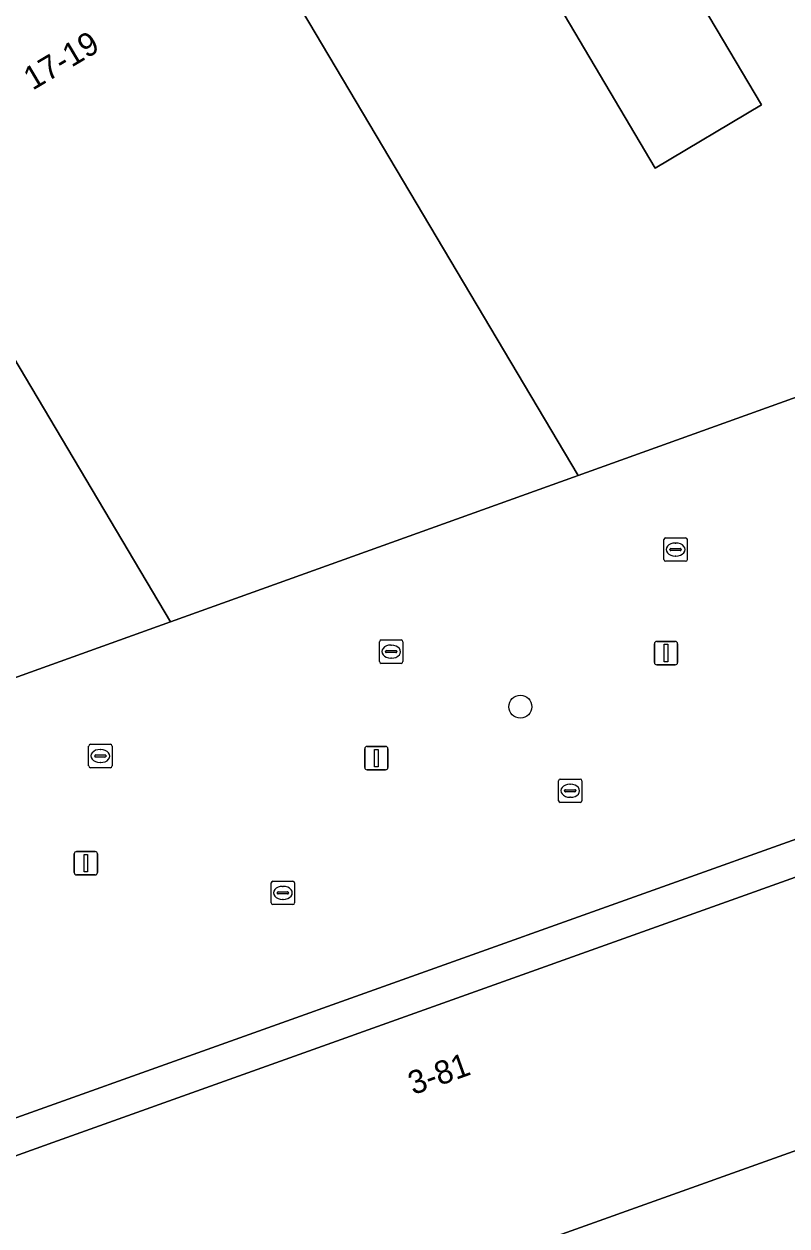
# Model space of a CAD drawing. Extents: x 159499 to 160349, y 382524 to 383273.
# Drawn here: x 159623.7 to 159656.3, y 382937.3 to 382988.7 of the extents above; entities that cross this region are included whole.
import ezdxf

# ---------------------------------------------------------------- set-up
doc = ezdxf.new("R2010")
doc.units = 0
for name, color, linetype in [('IMGEO_Boom', 7, 'Continuous'), ('IMGEO_Erf', 7, 'Continuous'), ('IMGEO_Groenvoorziening', 7, 'Continuous'), ('IMGEO_Kolk', 7, 'Continuous'), ('IMGEO_Lichtmast', 7, 'Continuous'), ('IMGEO_Pand', 7, 'Continuous'), ('IMGEO_Pand_nummerreeks', 7, 'Continuous'), ('IMGEO_Parkeervlak_open', 7, 'Continuous'), ('IMGEO_Voetpad_open', 7, 'Continuous')]:
    doc.layers.add(name, color=color, linetype=linetype)

msp = doc.modelspace()

# ---------------------------------------------------------------- linework, layer by layer
at = {"layer": 'IMGEO_Boom'}
msp.add_circle((159644.9, 382959.472), 0.489, dxfattribs=at)
at = {"layer": 'IMGEO_Erf'}
msp.add_lwpolyline([(159644.178, 383001.574), (159640.635, 382999.47), (159642.929, 382995.586), (159650.661, 382982.501), (159655.211, 382985.203), (159647.452, 382998.271), (159646.481, 382997.695)], close=True, dxfattribs=at)
at = {"layer": 'IMGEO_Groenvoorziening'}
msp.add_lwpolyline([(159685.537, 382944.38), (159682.676, 382958.981), (159682.454, 382960.802), (159675.818, 382961.931), (159676.134, 382961.046), (159680.442, 382948.993), (159609.134, 382923.507), (159606.674, 382930.391), (159601.595, 382928.556), (159605.894, 382916.702)], dxfattribs=at)
at = {"layer": 'IMGEO_Kolk'}
for p, q in [((159651.11, 382966.69), (159651.962, 382966.69)), ((159651.035, 382965.764), (159651.035, 382966.616)), ((159651.294, 382966.184), (159651.294, 382966.196)), ((159651.732, 382966.147), (159651.334, 382966.147)), ((159651.337, 382966.233), (159651.735, 382966.233)), ((159651.523, 382966.47), (159651.548, 382966.47)), ((159651.778, 382966.196), (159651.778, 382966.184)), ((159652.036, 382966.616), (159652.036, 382965.764)), ((159651.962, 382965.69), (159651.11, 382965.69)), ((159651.546, 382965.91), (159651.521, 382965.91)), ((159638.877, 382961.4), (159638.877, 382962.252)), ((159638.952, 382962.326), (159639.804, 382962.326)), ((159639.365, 382962.106), (159639.39, 382962.106)), ((159639.878, 382962.252), (159639.878, 382961.4)), ((159639.136, 382961.82), (159639.136, 382961.832)), ((159639.574, 382961.783), (159639.176, 382961.783)), ((159639.179, 382961.869), (159639.577, 382961.869)), ((159639.388, 382961.546), (159639.363, 382961.546)), ((159639.62, 382961.832), (159639.62, 382961.82)), ((159639.804, 382961.326), (159638.952, 382961.326)), ((159626.445, 382956.938), (159626.445, 382957.79)), ((159626.52, 382957.864), (159627.372, 382957.864)), ((159626.747, 382957.407), (159627.145, 382957.407)), ((159626.933, 382957.644), (159626.958, 382957.644)), ((159627.446, 382957.79), (159627.446, 382956.938)), ((159626.704, 382957.358), (159626.704, 382957.37)), ((159627.142, 382957.321), (159626.744, 382957.321)), ((159626.956, 382957.084), (159626.931, 382957.084)), ((159627.188, 382957.37), (159627.188, 382957.358)), ((159627.372, 382956.864), (159626.52, 382956.864)), ((159646.604, 382956.38), (159647.456, 382956.38)), ((159646.529, 382955.454), (159646.529, 382956.306)), ((159646.788, 382955.874), (159646.788, 382955.886)), ((159646.831, 382955.923), (159647.229, 382955.923)), ((159647.017, 382956.16), (159647.042, 382956.16)), ((159647.272, 382955.886), (159647.272, 382955.874)), ((159647.53, 382956.306), (159647.53, 382955.454)), ((159647.456, 382955.38), (159646.604, 382955.38)), ((159647.226, 382955.837), (159646.828, 382955.837)), ((159647.04, 382955.6), (159647.015, 382955.6)), ((159634.249, 382951.083), (159634.249, 382951.935)), ((159634.324, 382952.009), (159635.176, 382952.009)), ((159634.737, 382951.789), (159634.762, 382951.789)), ((159635.25, 382951.935), (159635.25, 382951.083)), ((159634.508, 382951.503), (159634.508, 382951.515)), ((159634.946, 382951.466), (159634.548, 382951.466)), ((159634.551, 382951.552), (159634.949, 382951.552)), ((159634.992, 382951.515), (159634.992, 382951.503)), ((159635.176, 382951.009), (159634.324, 382951.009)), ((159634.76, 382951.229), (159634.735, 382951.229))]:
    msp.add_line(p, q, dxfattribs=at)
for points in [[(159651.11, 382966.69), (159651.962, 382966.69)], [(159651.035, 382965.764), (159651.035, 382966.616)], [(159652.036, 382966.616), (159652.036, 382965.764)], [(159651.962, 382965.69), (159651.11, 382965.69)], [(159638.877, 382961.4), (159638.877, 382962.252)], [(159638.952, 382962.326), (159639.804, 382962.326)], [(159639.878, 382962.252), (159639.878, 382961.4)], [(159639.804, 382961.326), (159638.952, 382961.326)], [(159626.445, 382956.938), (159626.445, 382957.79)], [(159626.52, 382957.864), (159627.372, 382957.864)], [(159627.446, 382957.79), (159627.446, 382956.938)], [(159627.372, 382956.864), (159626.52, 382956.864)], [(159646.604, 382956.38), (159647.456, 382956.38)], [(159646.529, 382955.454), (159646.529, 382956.306)], [(159647.53, 382956.306), (159647.53, 382955.454)], [(159647.456, 382955.38), (159646.604, 382955.38)], [(159634.249, 382951.083), (159634.249, 382951.935)], [(159634.324, 382952.009), (159635.176, 382952.009)], [(159635.25, 382951.935), (159635.25, 382951.083)], [(159635.176, 382951.009), (159634.324, 382951.009)]]:
    msp.add_lwpolyline(points, dxfattribs=at)
for centre, radius, start, end in [((159651.112, 382966.614), 0.0765, 91.552, 178.448), ((159651.112, 382966.614), 0.0765, 91.552, 178.448), ((159651.96, 382966.614), 0.0765, 1.552, 88.448), ((159651.96, 382966.614), 0.0765, 1.552, 88.448), ((159651.334, 382966.193), 0.0403, 85.8775, 175.7526), ((159651.331, 382966.183), 0.0366, 178.938, 274.7102), ((159651.735, 382966.19), 0.043, 264.8664, 352.4533), ((159651.739, 382966.195), 0.0386, 1.7309, 96.639), ((159651.112, 382965.766), 0.0765, 181.552, 268.448), ((159651.112, 382965.766), 0.0765, 181.552, 268.448), ((159651.96, 382965.766), 0.0765, 271.552, 358.448), ((159651.96, 382965.766), 0.0765, 271.552, 358.448), ((159638.954, 382962.25), 0.0765, 91.552, 178.448), ((159638.954, 382962.25), 0.0765, 91.552, 178.448), ((159639.802, 382962.25), 0.0765, 1.552, 88.448), ((159639.802, 382962.25), 0.0765, 1.552, 88.448), ((159639.176, 382961.829), 0.0403, 85.8775, 175.7526), ((159639.173, 382961.819), 0.0366, 178.938, 274.7102), ((159639.577, 382961.826), 0.043, 264.8664, 352.4533), ((159639.581, 382961.831), 0.0386, 1.7309, 96.639), ((159638.954, 382961.402), 0.0765, 181.552, 268.448), ((159638.954, 382961.402), 0.0765, 181.552, 268.448), ((159639.802, 382961.402), 0.0765, 271.552, 358.448), ((159639.802, 382961.402), 0.0765, 271.552, 358.448), ((159626.522, 382957.788), 0.0765, 91.552, 178.448), ((159626.522, 382957.788), 0.0765, 91.552, 178.448), ((159626.744, 382957.367), 0.0403, 85.8775, 175.7526), ((159627.149, 382957.369), 0.0386, 1.7309, 96.639), ((159627.37, 382957.788), 0.0765, 1.552, 88.448), ((159627.37, 382957.788), 0.0765, 1.552, 88.448), ((159626.522, 382956.94), 0.0765, 181.552, 268.448), ((159626.522, 382956.94), 0.0765, 181.552, 268.448), ((159626.741, 382957.357), 0.0366, 178.938, 274.7102), ((159627.145, 382957.364), 0.043, 264.8664, 352.4533), ((159627.37, 382956.94), 0.0765, 271.552, 358.448), ((159627.37, 382956.94), 0.0765, 271.552, 358.448), ((159646.606, 382956.304), 0.0765, 91.552, 178.448), ((159646.606, 382956.304), 0.0765, 91.552, 178.448), ((159647.454, 382956.304), 0.0765, 1.552, 88.448), ((159647.454, 382956.304), 0.0765, 1.552, 88.448), ((159646.828, 382955.883), 0.0403, 85.8775, 175.7526), ((159646.825, 382955.873), 0.0366, 178.938, 274.7102), ((159647.229, 382955.88), 0.043, 264.8664, 352.4533), ((159647.233, 382955.885), 0.0386, 1.7309, 96.639), ((159646.606, 382955.456), 0.0765, 181.552, 268.448), ((159646.606, 382955.456), 0.0765, 181.552, 268.448), ((159647.454, 382955.456), 0.0765, 271.552, 358.448), ((159647.454, 382955.456), 0.0765, 271.552, 358.448), ((159634.326, 382951.933), 0.0765, 91.552, 178.448), ((159634.326, 382951.933), 0.0765, 91.552, 178.448), ((159635.174, 382951.933), 0.0765, 1.552, 88.448), ((159635.174, 382951.933), 0.0765, 1.552, 88.448), ((159634.548, 382951.512), 0.0403, 85.8775, 175.7526), ((159634.545, 382951.502), 0.0366, 178.938, 274.7102), ((159634.949, 382951.509), 0.043, 264.8664, 352.4533), ((159634.953, 382951.514), 0.0386, 1.7309, 96.639), ((159634.326, 382951.085), 0.0765, 181.552, 268.448), ((159634.326, 382951.085), 0.0765, 181.552, 268.448), ((159635.174, 382951.085), 0.0765, 271.552, 358.448), ((159635.174, 382951.085), 0.0765, 271.552, 358.448)]:
    msp.add_arc(centre, radius, start, end, dxfattribs=at)
for centre, major_axis, ratio, start_param, end_param in [((159651.522, 382966.19), (-0.387, 0.002), 0.722429, 4.712389, 7.853982), ((159651.547, 382966.19), (-0.39, 0.002), 0.717154, 1.570796, 4.712389), ((159639.364, 382961.826), (-0.387, 0.002), 0.722429, 4.712389, 7.853982), ((159639.389, 382961.826), (-0.39, 0.002), 0.717154, 1.570796, 4.712389), ((159626.932, 382957.364), (-0.387, 0.002), 0.722429, 4.712389, 7.853982), ((159626.957, 382957.364), (-0.39, 0.002), 0.717154, 1.570796, 4.712389), ((159647.016, 382955.88), (-0.387, 0.002), 0.722429, 4.712389, 7.853982), ((159647.041, 382955.88), (-0.39, 0.002), 0.717154, 1.570796, 4.712389), ((159634.736, 382951.509), (-0.387, 0.002), 0.722429, 4.712389, 7.853982), ((159634.761, 382951.509), (-0.39, 0.002), 0.717154, 1.570796, 4.712389)]:
    msp.add_ellipse(centre, major_axis=major_axis, ratio=ratio, start_param=start_param, end_param=end_param, dxfattribs=at)
at = {"layer": 'IMGEO_Lichtmast'}
for p, q in [((159650.631, 382961.365), (159650.631, 382962.165)), ((159650.631, 382962.165), (159650.631, 382961.365)), ((159650.731, 382962.265), (159651.521, 382962.265)), ((159651.521, 382962.265), (159650.731, 382962.265)), ((159651.621, 382962.165), (159651.621, 382961.365)), ((159651.621, 382961.365), (159651.621, 382962.165)), ((159651.521, 382961.265), (159650.731, 382961.265)), ((159650.731, 382961.265), (159651.521, 382961.265)), ((159638.248, 382956.872), (159638.248, 382957.672)), ((159638.248, 382957.672), (159638.248, 382956.872)), ((159638.348, 382957.772), (159639.138, 382957.772)), ((159639.138, 382957.772), (159638.348, 382957.772)), ((159639.238, 382957.672), (159639.238, 382956.872)), ((159639.238, 382956.872), (159639.238, 382957.672)), ((159639.138, 382956.772), (159638.348, 382956.772)), ((159638.348, 382956.772), (159639.138, 382956.772)), ((159625.83, 382952.381), (159625.83, 382953.181)), ((159625.83, 382953.181), (159625.83, 382952.381)), ((159625.93, 382953.281), (159626.72, 382953.281)), ((159626.72, 382953.281), (159625.93, 382953.281)), ((159626.82, 382953.181), (159626.82, 382952.381)), ((159626.82, 382952.381), (159626.82, 382953.181)), ((159626.72, 382952.281), (159625.93, 382952.281)), ((159625.93, 382952.281), (159626.72, 382952.281))]:
    msp.add_line(p, q, dxfattribs=at)
for points in [[(159651.051, 382962.14), (159651.201, 382962.14), (159651.201, 382961.39), (159651.051, 382961.39), (159651.051, 382962.14)], [(159638.668, 382957.647), (159638.818, 382957.647), (159638.818, 382956.897), (159638.668, 382956.897), (159638.668, 382957.647)], [(159626.25, 382953.156), (159626.4, 382953.156), (159626.4, 382952.406), (159626.25, 382952.406), (159626.25, 382953.156)]]:
    msp.add_lwpolyline(points, dxfattribs=at)
for centre, start, end in [((159650.731, 382962.165), 90, 180), ((159650.731, 382962.165), 90, 180), ((159651.521, 382962.165), 0, 90), ((159651.521, 382962.165), 360, 90), ((159650.731, 382961.365), 180, 270), ((159650.731, 382961.365), 180, 270), ((159651.521, 382961.365), 270, 0), ((159651.521, 382961.365), 270, 0), ((159638.348, 382957.672), 90, 180), ((159638.348, 382957.672), 90, 180), ((159639.138, 382957.672), 0, 90), ((159639.138, 382957.672), 360, 90), ((159638.348, 382956.872), 180, 270), ((159638.348, 382956.872), 180, 270), ((159639.138, 382956.872), 270, 0), ((159639.138, 382956.872), 270, 0), ((159625.93, 382953.181), 90, 180), ((159625.93, 382953.181), 90, 180), ((159626.72, 382953.181), 0, 90), ((159626.72, 382953.181), 360, 90), ((159625.93, 382952.381), 180, 270), ((159625.93, 382952.381), 180, 270), ((159626.72, 382952.381), 270, 0), ((159626.72, 382952.381), 270, 0)]:
    msp.add_arc(centre, 0.1, start, end, dxfattribs=at)
at = {"layer": 'IMGEO_Pand'}
for points in [[(159663.847, 382989.981), (159657.898, 383000), (159653.631, 383007.187), (159644.178, 383001.574), (159646.481, 382997.695), (159647.452, 382998.271), (159655.211, 382985.203), (159650.661, 382982.501), (159642.929, 382995.586), (159640.635, 382999.47), (159632.4, 382994.581), (159647.373, 382969.363), (159665.691, 382975.944), (159668.441, 382976.932), (159667.344, 382979.99)], [(159616.76, 382985.295), (159629.938, 382963.1), (159647.373, 382969.363), (159632.4, 382994.581)], [(159594.075, 382950.274), (159598.105, 382951.722), (159615.784, 382958.015), (159629.938, 382963.1), (159616.76, 382985.295), (159587.366, 382967.842), (159587.852, 382966.52), (159588.22, 382966.653)], [(159622.779, 382941.693), (159621.91, 382944.124), (159621.758, 382944.07), (159613.077, 382940.968), (159614.525, 382937.123), (159605.702, 382933.97), (159605.077, 382935.718), (159604.805, 382935.62), (159604.862, 382935.46), (159606.674, 382930.391), (159609.134, 382923.507), (159680.442, 382948.993), (159676.134, 382961.046), (159676.022, 382961.006), (159675.913, 382960.967), (159676.004, 382960.713), (159676.516, 382959.279), (159624.918, 382940.838), (159623.292, 382940.257)]]:
    msp.add_lwpolyline(points, close=True, dxfattribs=at)
at = {"layer": 'IMGEO_Parkeervlak_open'}
for points in [[(159668.684, 382959.557), (159675.525, 382961.982), (159674.596, 382964.728), (159674.339, 382965.486), (159672.61, 382965.844), (159669.28, 382966.514), (159667.737, 382970.948), (159664.183, 382972.651), (159665.691, 382975.944), (159647.373, 382969.363), (159629.938, 382963.1), (159615.784, 382958.015)], [(159622.779, 382941.693), (159667.453, 382957.657)]]:
    msp.add_lwpolyline(points, dxfattribs=at)
at = {"layer": 'IMGEO_Voetpad_open'}
msp.add_lwpolyline([(159624.918, 382940.838), (159676.516, 382959.279), (159676.004, 382960.713), (159667.453, 382957.657), (159622.779, 382941.693), (159623.292, 382940.257)], close=True, dxfattribs=at)

# ---------------------------------------------------------------- texts
at = {"layer": 'IMGEO_Pand_nummerreeks'}
for s, rotation, p in [('17-19', 30.699, (159624.048, 382985.807)), ('3-81', 19.6669, (159640.319, 382942.859))]:
    msp.add_text(s, height=1, rotation=rotation, dxfattribs=at).set_placement(p)

doc.saveas('drawing.dxf')
